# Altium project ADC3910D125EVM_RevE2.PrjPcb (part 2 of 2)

## Sheet ADC3910D125EVM_USB_Control_RevE2.SchDoc
size 431 x 279 mm; Date: Not shown in title block; ApprovedBy: Not shown in title block; CheckedBy: Not shown in title block; Author: Not shown in title block; CompanyName: Not shown in title block; Engineer: Not shown in title block; Organization: Not shown in title block; Address1: Not shown in title block; Address2: Not shown in title block; Address3: Not shown in title block; Address4: Not shown in title block; DocumentNumber: 3; Revision: Use project parameter SCH_Rev; SheetNumber: 5; SheetTotal: 7; PageSetup: Record=PageOptions¦CenterHorizontal=True¦CenterVertical=True¦PrintScale=1.00¦XCorrection=1.00¦YCorrection=1.00¦PrintKind=0¦BorderSize=5000000¦LeftOffset=0¦BottomOffset=0¦Orientation=2¦PaperLength=1000¦PaperWidth=1000¦Scale=100¦PaperSource=15¦PrintQuality=600¦MediaType=1¦DitherType=10¦PaperKind=Letter¦PrintScaleMode=1
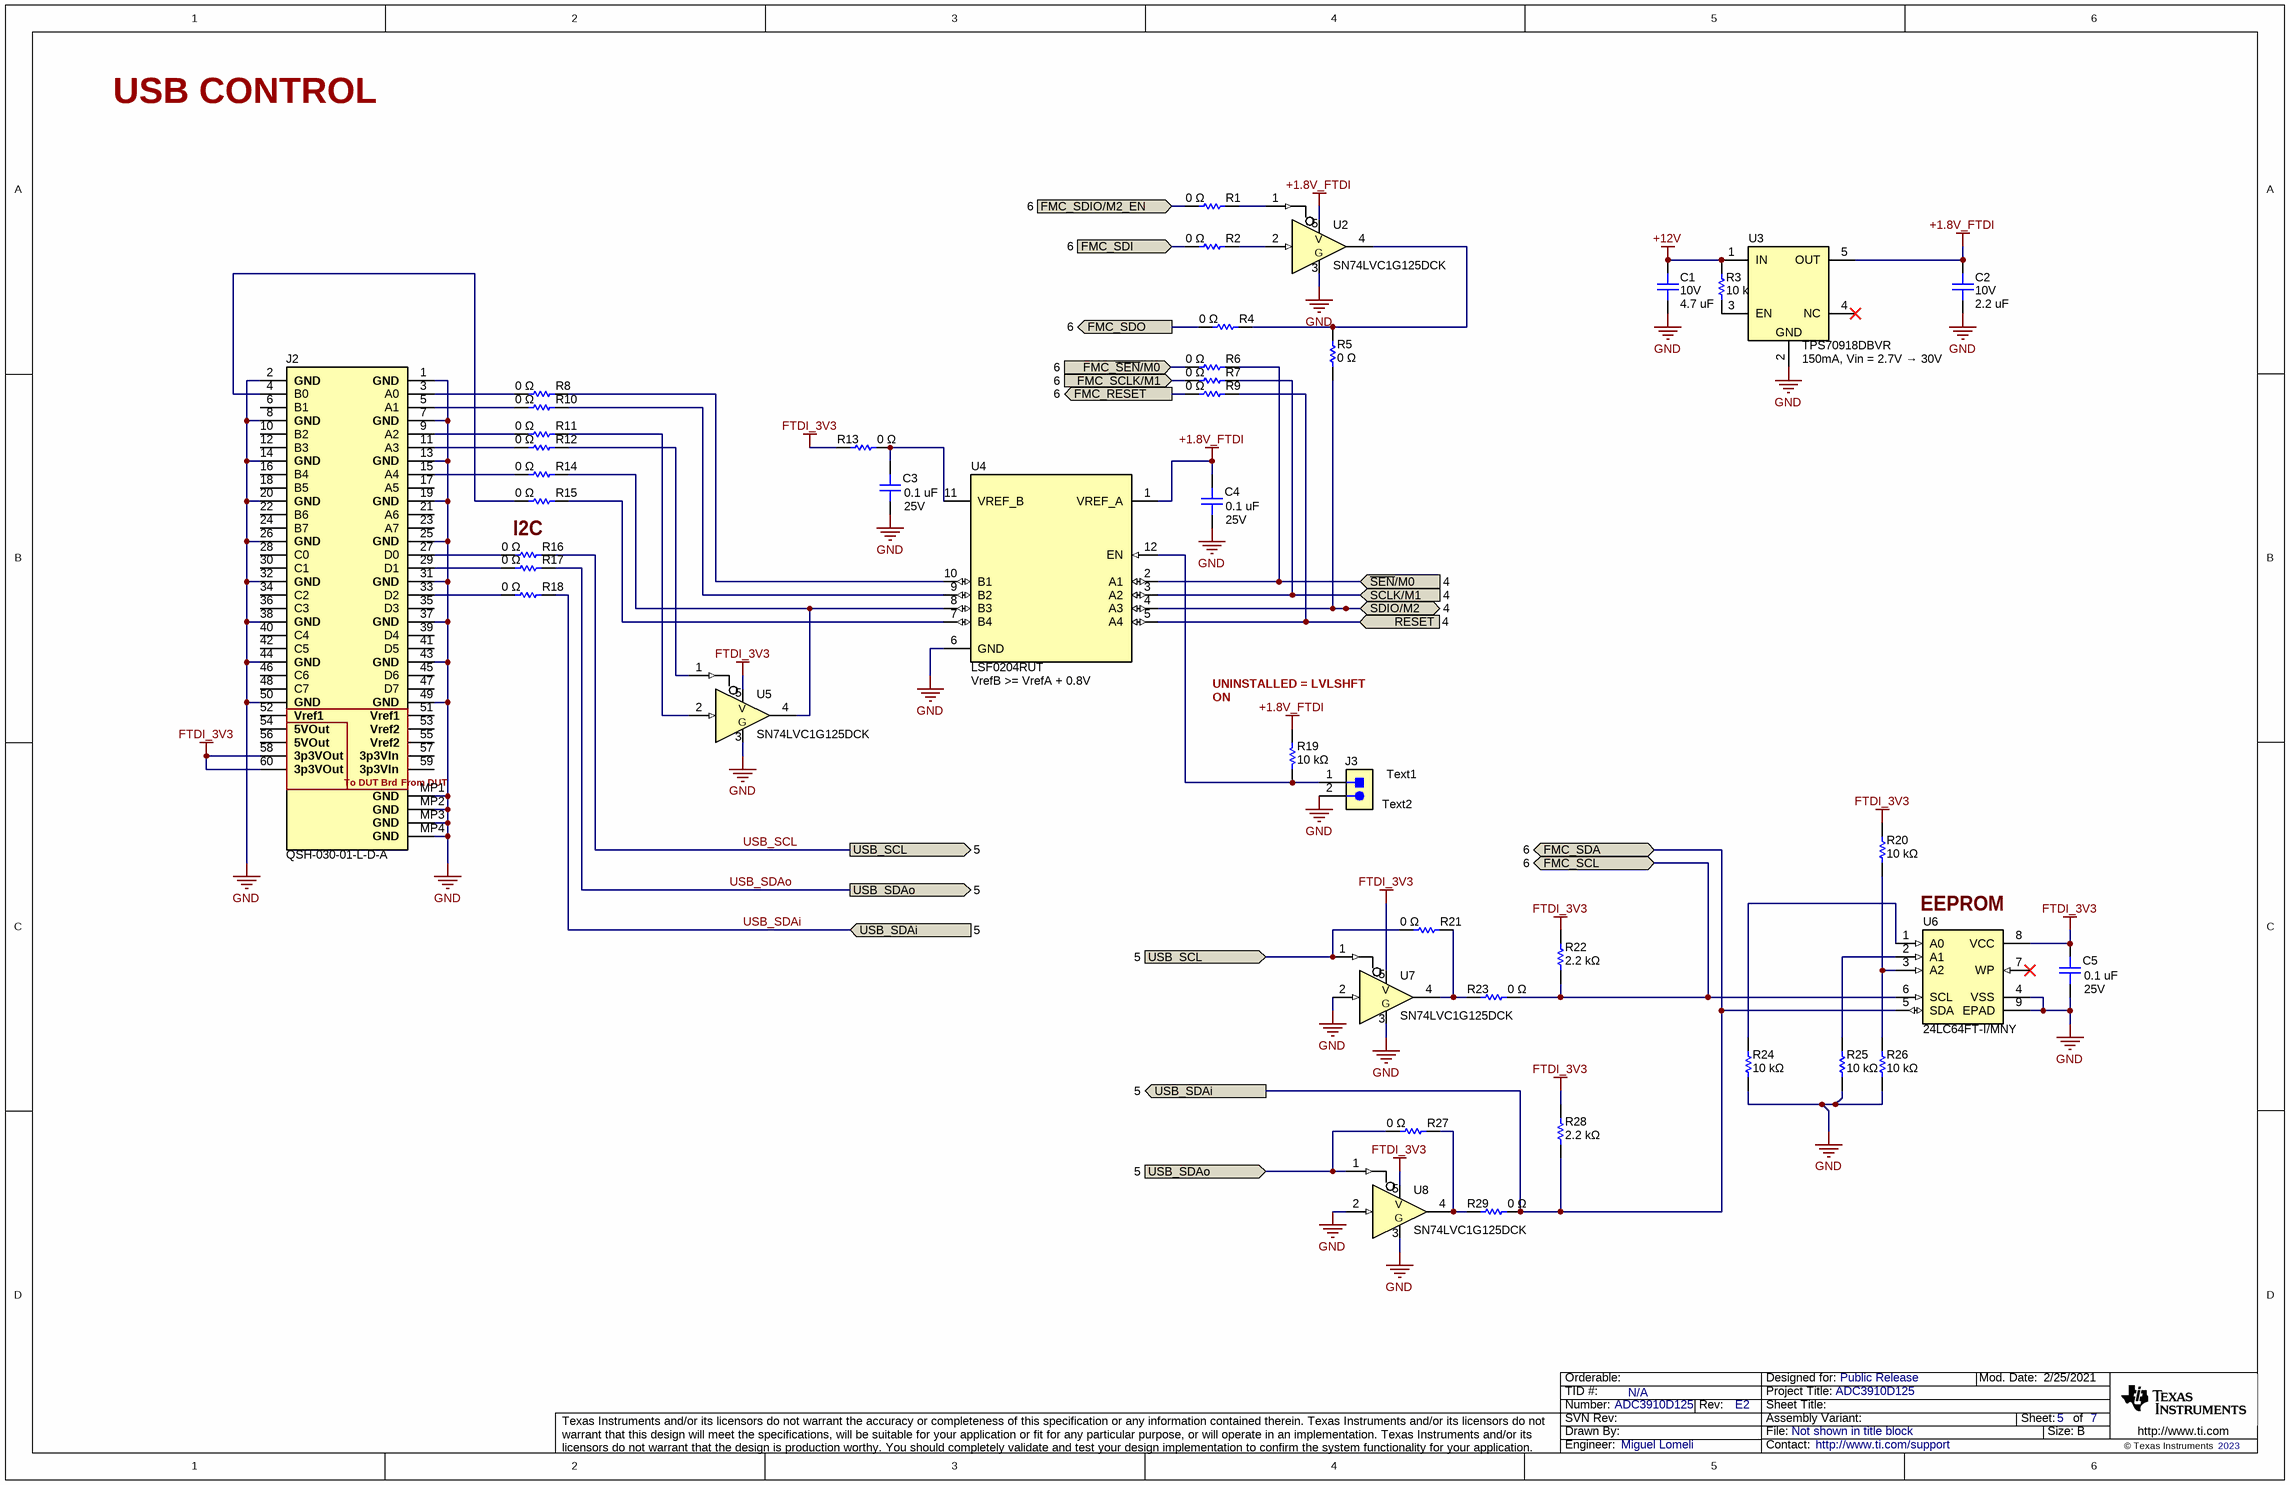
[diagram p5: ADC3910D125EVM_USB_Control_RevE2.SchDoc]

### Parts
C1  value 4.7 uF  Voltage - Rated: 10V  [0402L_cap]  (hidden comment: C1005X5R1A475K050BC)
C2  value 2.2 uF  Voltage - Rated: 10V  [0402L_cap]  (hidden comment: CM05X5R225K10AH)
C3  value 0.1 uF  Voltage - Rated: 25V  [0402L_cap]  (hidden comment: GRT155R71E104KE01J)
C4  value 0.1 uF  Voltage - Rated: 25V  [0402L_cap]  (hidden comment: GRT155R71E104KE01J)
C5  value 0.1 uF  Voltage - Rated: 25V  [0402L_cap]  (hidden comment: GRT155R71E104KE01J)
J2  QSH-030-01-L-D-A  [FTDI_Dongle_003]
J3  PBC02SAAN  [PBC02SAAN]  (value not drawn)
R1  value 0 Ω  [0201]  (hidden comment: ERJ-1GN0R00C)
R2  value 0 Ω  [0201]  (hidden comment: ERJ-1GN0R00C)
R3  value 10 kΩ  [0402L]  (hidden comment: ERJ-2RKF1002X)
R4  value 0 Ω  [0201]  (hidden comment: ERJ-1GN0R00C)
R5  value 0 Ω  [0201]  (hidden comment: ERJ-1GN0R00C)
R6  value 0 Ω  [0201]  (hidden comment: ERJ-1GN0R00C)
R7  value 0 Ω  [0201]  (hidden comment: ERJ-1GN0R00C)
R8  value 0 Ω  [0402L]  (hidden comment: ERJ-2GE0R00X)
R9  value 0 Ω  [0201]  (hidden comment: ERJ-1GN0R00C)
R10  value 0 Ω  [0402L]  (hidden comment: ERJ-2GE0R00X)
R11  value 0 Ω  [0402L]  (hidden comment: ERJ-2GE0R00X)
R12  value 0 Ω  [0402L]  (hidden comment: ERJ-2GE0R00X)
R13  value 0 Ω  [0402L]  (hidden comment: ERJ-2GE0R00X)
R14  value 0 Ω  [0402L]  (hidden comment: ERJ-2GE0R00X)
R15  value 0 Ω  [0402L]  (hidden comment: ERJ-2GE0R00X)
R16  value 0 Ω  [0402L]  (hidden comment: ERJ-2GE0R00X)
R17  value 0 Ω  [0402L]  (hidden comment: ERJ-2GE0R00X)
R18  value 0 Ω  [0402L]  (hidden comment: ERJ-2GE0R00X)
R19  value 10 kΩ  [0402L]  (hidden comment: ERJ-2GEJ103X)
R20  value 10 kΩ  [0402L]  (hidden comment: ERJ-2GEJ103X)
R21  value 0 Ω  [0201]  (hidden comment: ERJ-1GN0R00C)
R22  value 2.2 kΩ  [0402L]  (hidden comment: ERJ-2GEJ222X)
R23  value 0 Ω  [0402L]  (hidden comment: ERJ-2GE0R00X)
R24  value 10 kΩ  [0402L]  (hidden comment: ERJ-2GEJ103X)
R25  value 10 kΩ  [0402L]  (hidden comment: ERJ-2GEJ103X)
R26  value 10 kΩ  [0402L]  (hidden comment: ERJ-2GEJ103X)
R27  value 0 Ω  [0201]  (hidden comment: ERJ-1GN0R00C)
R28  value 2.2 kΩ  [0402L]  (hidden comment: ERJ-2GEJ222X)
R29  value 0 Ω  [0402L]  (hidden comment: ERJ-2GE0R00X)
U2  SN74LVC1G125DCK  [DCK0005A]
U3  TPS70918DBVR  Text1: 150mA, Vin = 2.7V → 30V  [DBV0005A]
U4  LSF0204RUT  Text1: VrefB >= VrefA + 0.8V  [RUT0012A]
U5  SN74LVC1G125DCK  [DCK0005A]
U6  24LC64FT-I/MNY  [TDFN8]
U7  SN74LVC1G125DCK  [DCK0005A]
U8  SN74LVC1G125DCK  [DCK0005A]

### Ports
FMC_RESET (out, see 6), FMC_SCL (bidir, see 6), FMC_SCLK/M1 (in, see 6), FMC_SDA (bidir, see 6), FMC_SDI (in, see 6), FMC_SDIO/M2_EN (in, see 6), FMC_SDO (out, see 6), FMC_~{SEN}/M0 (in, see 6), RESET (in, see 4), SCLK/M1 (in, see 4), SDIO/M2 (bidir, see 4), USB_SCL (in, see 5), USB_SCL (out, see 5), USB_SDAi (in, see 5), USB_SDAi (out, see 5), USB_SDAo (in, see 5), USB_SDAo (out, see 5), ~{SEN}/M0 (in, see 4)

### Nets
+1.8V_FTDI: C2.2 C4.2 R19.2 U2.5(VCC) U3.5(OUT) U4.1(VREF_A)
+12V: C1.2 R3.2 U3.1(IN)
FTDI_3V3: C5.2 J2.58(3p3VOut) J2.60(3p3VOut) R13.1 R20.2 R22.2 R28.2 U5.5(VCC) U6.8(VCC) U7.5(VCC) U8.5(VCC)
GND: C1.1 C2.1 C3.1 C4.1 C5.1 J2.1(GND) J2.2(GND) J2.7(GND) J2.8(GND) J2.13(GND) J2.14(GND) J2.19(GND) J2.20(GND) J2.25(GND) J2.26(GND) J2.31(GND) J2.32(GND) J2.37(GND) J2.38(GND) J2.43(GND) J2.44(GND) J2.49(GND) J2.50(GND) J2.MP1(GND) J2.MP2(GND) J2.MP3(GND) J2.MP4(GND) J3.2 R24.1 R25.1 R26.1 U2.3(GND) U3.2(GND) U4.6(GND) U5.3(GND) U6.4(VSS) U6.9(EPAD) U7.2(A) U7.3(GND) U8.2(A) U8.3(GND)
FMC_RESET: R9.1 ; port FMC_RESET
FMC_~{SEN}/M0: R6.1 ; port FMC_~{SEN}/M0
FMC_SCL: R22.1 R23.2 U6.6(SCL) ; port FMC_SCL
FMC_SCLK/M1: R7.1 ; port FMC_SCLK/M1
FMC_SDI: R2.1 ; port FMC_SDI
FMC_SDIO/M2_EN: R1.1 ; port FMC_SDIO/M2_EN
FMC_SDO: R4.1 ; port FMC_SDO
RESET: R9.2 U4.5(A4) ; port RESET
~{SEN}/M0: R6.2 U4.2(A1) ; port ~{SEN}/M0
SCLK/M1: R7.2 U4.3(A2) ; port SCLK/M1
SDIO/M2: R5.1 U4.4(A3) ; port SDIO/M2
USB_SCL: R16.2 R21.1 U7.1(~{OE}) ; port USB_SCL
USB_SDAi: R18.2 R28.1 R29.2 U6.5(SDA) ; port USB_SDAi, port FMC_SDA
USB_SDAo: R17.2 R27.1 U8.1(~{OE}) ; port USB_SDAo
NetC3_2: C3.2 R13.2 U4.11(VREF_B)
NetJ2_3: J2.3(A0) R8.1
NetJ2_4: J2.4(B0) R15.1
NetJ2_5: J2.5(A1) R10.1
NetJ2_9: J2.9(A2) R11.1
NetJ2_11: J2.11(A3) R12.1
NetJ2_15: J2.15(A4) R14.1
NetJ2_27: J2.27(D0) R16.1
NetJ2_29: J2.29(D1) R17.1
NetJ2_33: J2.33(D2) R18.1
NetJ3_1: J3.1 R19.1 U4.12(EN)
NetR1_2: R1.2 U2.1(~{OE})
NetR2_2: R2.2 U2.2(A)
NetR3_1: R3.1 U3.3(EN)
NetR4_2: R4.2 R5.2 U2.4(Y)
NetR8_2: R8.2 U4.10(B1)
NetR10_2: R10.2 U4.9(B2)
NetR11_2: R11.2 U5.2(A)
NetR12_2: R12.2 U5.1(~{OE})
NetR14_2: R14.2 U4.8(B3) U5.4(Y)
NetR15_2: R15.2 U4.7(B4)
NetR20_1: R20.1 R26.2 U6.3(A2)
NetR21_2: R21.2 R23.1 U7.4(Y)
NetR24_2: R24.2 U6.1(A0)
NetR25_2: R25.2 U6.2(A1)
NetR27_2: R27.2 R29.1 U8.4(Y)

Not connected (* = marked no-connect by the designer): J2 6(B1) 10(B2) 12(B3) 16(B4) 17(A5) 18(B5) 21(A6) 22(B6) 23(A7) 24(B7) 28(C0) 30(C1) 34(C2) 35(D3) 36(C3) 39(D4) 40(C4) 41(D5) 42(C5) 45(D6) 46(C6) 47(D7) 48(C7) 51(Vref1) 52(Vref1) 53(Vref2) 54(5VOut) 55(Vref2) 56(5VOut) 57(3p3VIn) 59(3p3VIn); U3 4(NC)*; U6 7(WP)*

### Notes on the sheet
- USB CONTROL
- I2C
- (near R19) UNINSTALLED = LVLSHFT ON
  INSTALLED = LVLSHFT OFF
- (near U6) EEPROM

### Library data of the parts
C1 = capcc03298: CAP CER 4.7UF 10V X5R 0402; Manufacturer: TDK Corporation; CompType: Capacitor Ceramic; Tolerance: ±10%; SizeX_mm: 1; SizeY_mm: 0.5; SizeZ_mm: 0.65
C2 = capcc03230: CAP CER 2.2UF 10V X5R 0402; Manufacturer: KYOCERA AVX; CompType: Capacitor Ceramic; Tolerance: ±10%; SizeX_mm: 1; SizeY_mm: 0.5; SizeZ_mm: 0.55
C3-C5 = capcc09401: CAP CER 0.1UF 25V X7R 0402; Manufacturer: Murata; SizeZ_mm: 0.7; SizeX_mm: 1; SizeY_mm: 0.5; CompType: Capacitor Ceramic; Tolerance: ±10%
J2 = cmp00061: FTDI Dongle EVM Mating connector and standoff holes; Manufacturer: Samtec
J3 = cmp00014: Header, 100mil, 2x1, Gold, TH; Manufacturer: Sullins Connector Solutions; Pitch (mm): 2.54
R1 R2 R4-R7 R9 R21 R27 = RSMD020101699: RES SMD 0 OHM JUMPER 1/20W 0201; Manufacturer: Panasonic Electronic Components; CompType: Resistor SMD; Power (Watts): 0.05W, 1/20W
R3 = RSMD040200314: RES SMD 10K OHM 1% 1/10W 0402; Manufacturer: Panasonic Electronic Components; Power (Watts): 0.1W, 1/10W; Temperature Coefficient: ±100ppm/°C; SizeX_mm: 1; SizeY_mm: 0.5; SizeZ_mm: 0.4; CompType: Resistor SMD
R8 R10-R18 R23 R29 = RSMD040200001: RES SMD 0 OHM JUMPER 1/10W 0402; Manufacturer: Panasonic Electronic Components; CompType: Resistor SMD; Power (Watts): 0.1W, 1/10W; SizeX_mm: 1; SizeY_mm: 0.5; SizeZ_mm: 0.4
R19 R20 R24-R26 = RSMD040200306: RES SMD 10K OHM 5% 1/10W 0402; Manufacturer: Panasonic Electronic Components; CompType: Resistor SMD; Power (Watts): 0.1W, 1/10W; Temperature Coefficient: ±200ppm/°C; SizeX_mm: 1; SizeY_mm: 0.5; SizeZ_mm: 0.4
R22 R28 = RSMD040201206: RES SMD 2.2K OHM 5% 1/10W 0402; Manufacturer: Panasonic Electronic Components; CompType: Resistor SMD; Power (Watts): 0.1W, 1/10W; Temperature Coefficient: ±200ppm/°C; SizeX_mm: 1; SizeY_mm: 0.5; SizeZ_mm: 0.4
U2 U5 U7 U8 = cmp00143: Single Bus Buffer Gate With 3-State Outputs; Manufacturer: Texas Instruments
U3 = cmp00355: 150-mA, 30-V, ultra-low-IQ, low-dropout voltage regulator with reverse current protection and enable; Manufacturer: Texas Instruments; Alt PartNumber: TPS70918DBVT; CompType: LDO
U4 = cmp00182: 4-Bit Bidirectional Multi-Voltage Level Translator for Open-Drain & Push- Pull; Manufacturer: Texas Instruments; CompType: Level Shifter
U6 = cmp00154: EEPROM 64K 8KX8 1.8V SER EE IND 1/4AWP RPO; Manufacturer: Microchip

## Sheet ADC3910D125EVM_TSW1418_Header_RevE2.SchDoc
size 431 x 279 mm; Date: Not shown in title block; ApprovedBy: Not shown in title block; CheckedBy: Not shown in title block; Author: Not shown in title block; CompanyName: Not shown in title block; Engineer: Not shown in title block; Organization: Not shown in title block; Address1: Not shown in title block; Address2: Not shown in title block; Address3: Not shown in title block; Address4: Not shown in title block; DocumentNumber: 4; Revision: Use project parameter SCH_Rev; SheetNumber: 6; SheetTotal: 7; PageSetup: Record=PageOptions¦CenterHorizontal=True¦CenterVertical=True¦PrintScale=1.00¦XCorrection=1.00¦YCorrection=1.00¦PrintKind=0¦BorderSize=5000000¦LeftOffset=0¦BottomOffset=0¦Orientation=2¦PaperLength=1000¦PaperWidth=1000¦Scale=100¦PaperSource=15¦PrintQuality=600¦MediaType=1¦DitherType=10¦PaperKind=Letter¦PrintScaleMode=1
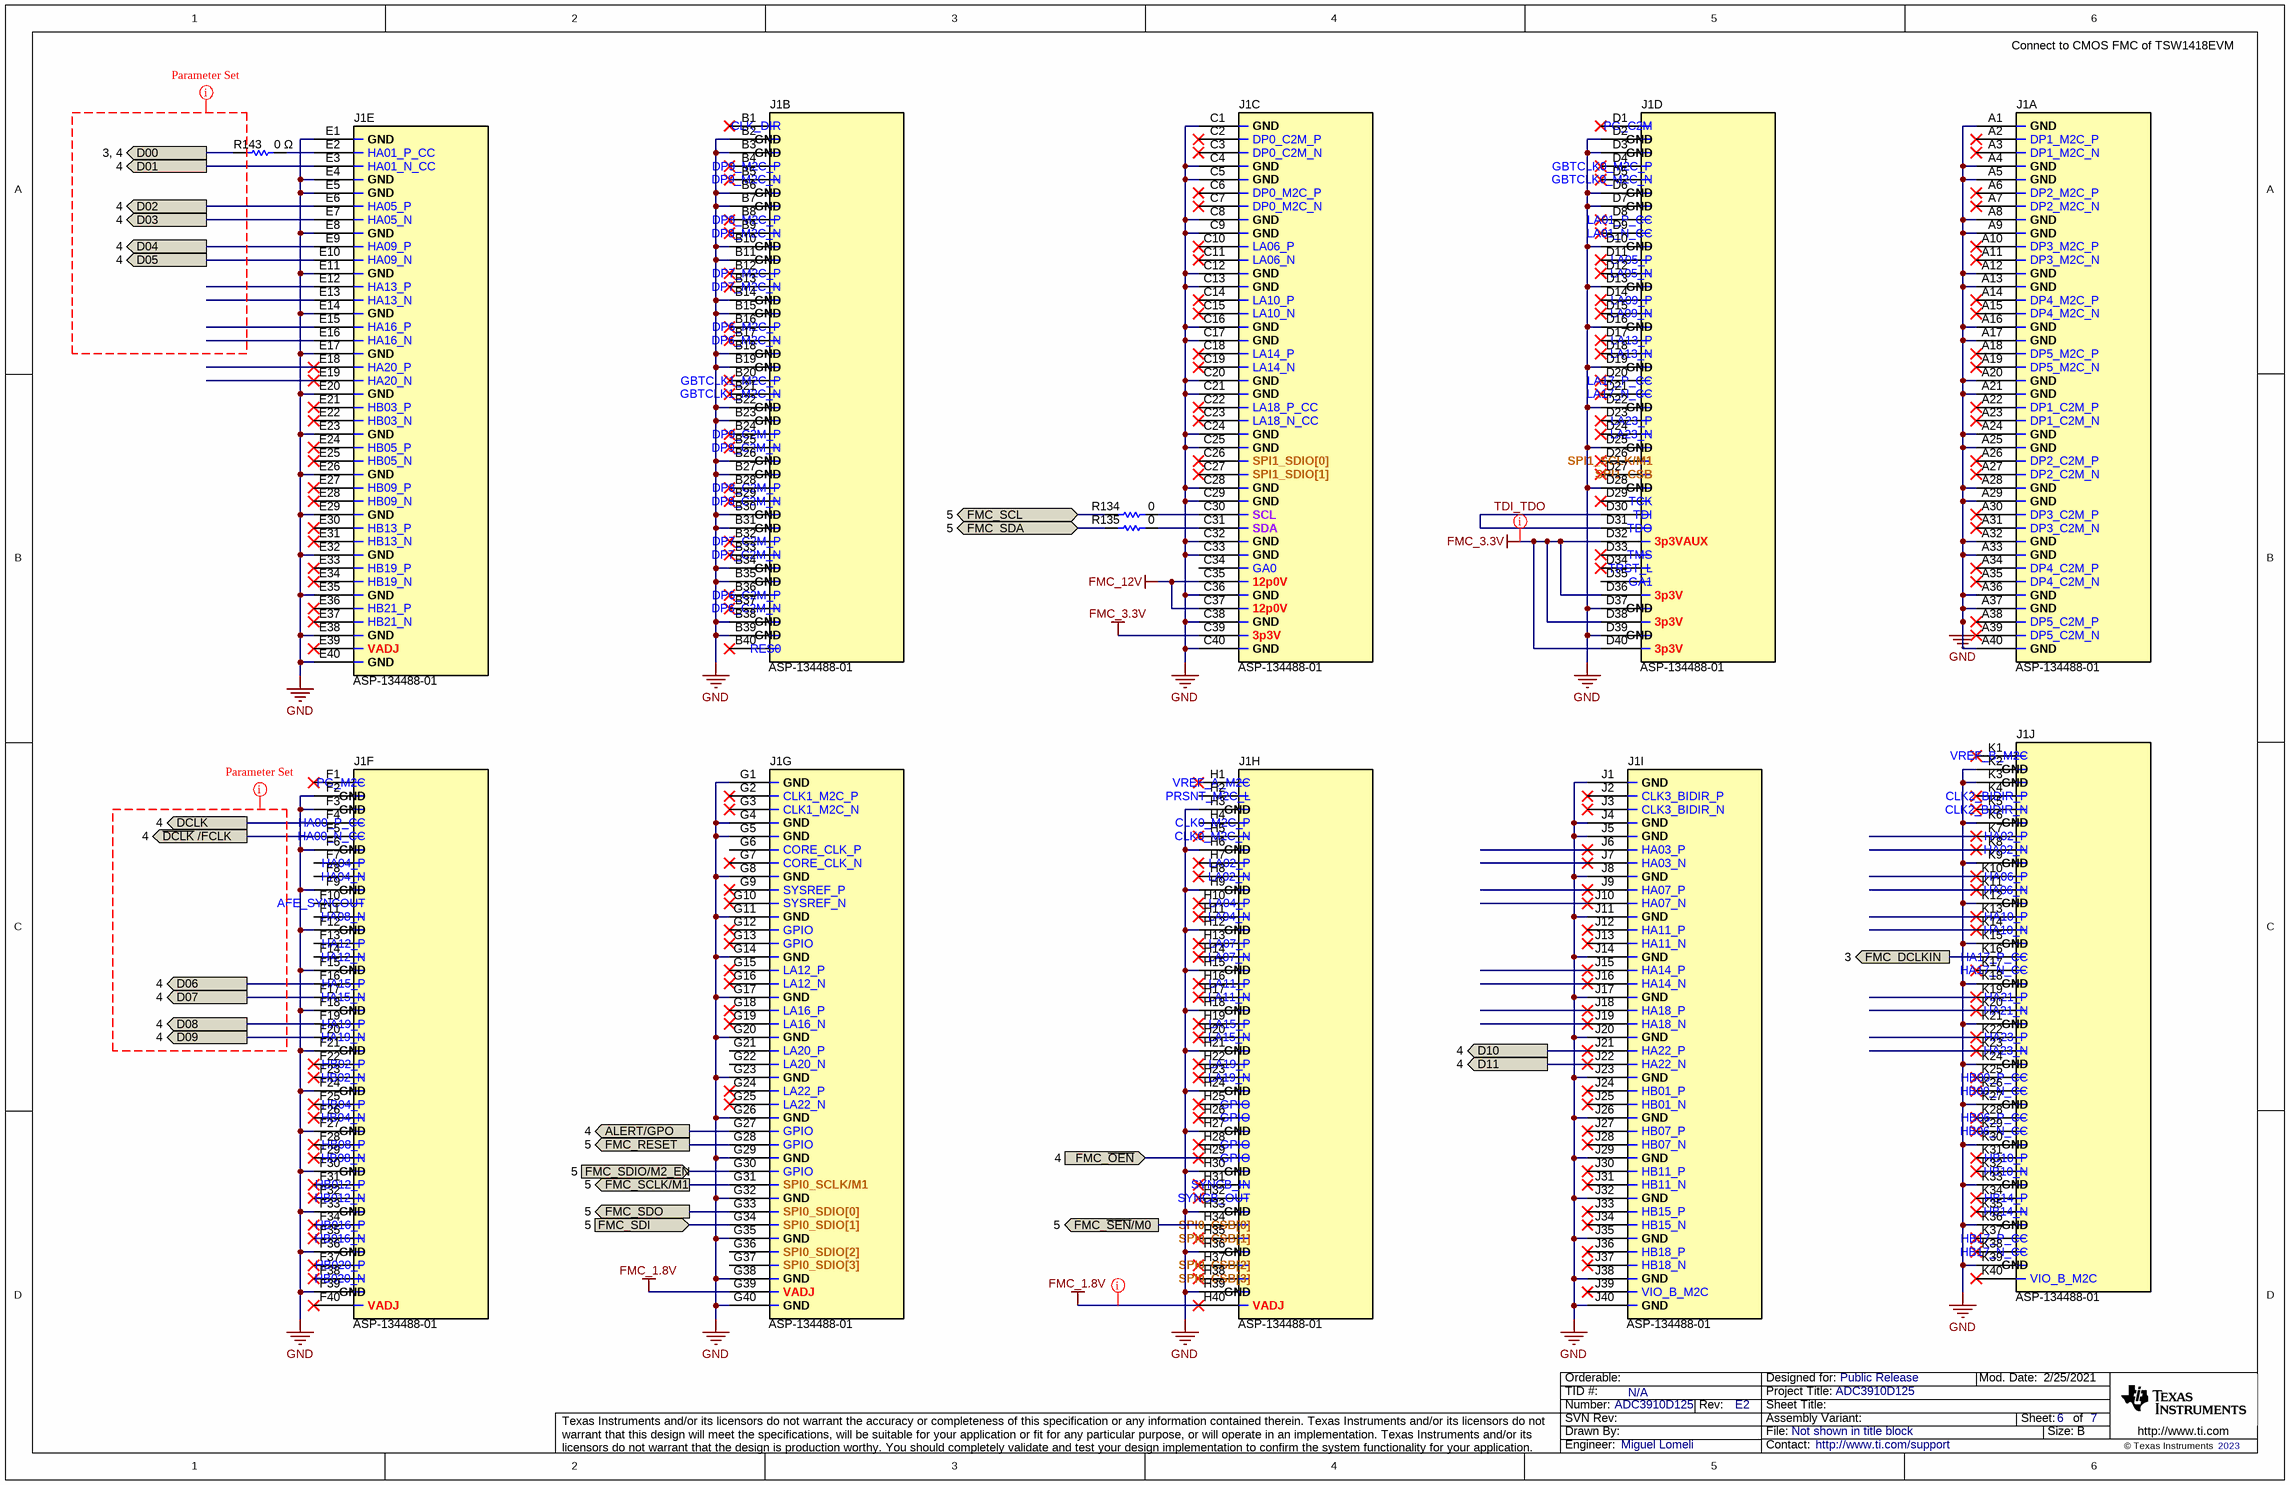
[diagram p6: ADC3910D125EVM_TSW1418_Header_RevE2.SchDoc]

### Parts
J1  ASP-134488-01  [SAMTEC_ASP-134488-01]  (parts A,B,C,D,E,F,G,H,I,J of 10)
R134  ValueDisplayed: 0  [0201L]  (hidden comment: CRCW02010000Z0ED)
R135  ValueDisplayed: 0  [0201L]  (hidden comment: CRCW02010000Z0ED)
R143  value 0 Ω  [0402L]  (hidden comment: ERJ-2GE0R00X)

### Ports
ALERT/GPO (out, see 4), D00 (out, see 3, 4), D01 (out, see 4), D02 (out, see 4), D03 (out, see 4), D04 (out, see 4), D05 (out, see 4), D06 (out, see 4), D07 (out, see 4), D08 (out, see 4), D09 (out, see 4), D10 (out, see 4), D11 (out, see 4), DCLK (out, see 4), FMC_DCLKIN (out, see 3), FMC_RESET (out, see 5), FMC_SCL (bidir, see 5), FMC_SCLK/M1 (out, see 5), FMC_SDA (bidir, see 5), FMC_SDI (in, see 5), FMC_SDIO/M2_EN (in, see 5), FMC_SDO (out, see 5), FMC_~{OEN} (in, see 4), FMC_~{SEN}/M0 (out, see 5), ~{DCLK} /FCLK (out, see 4)

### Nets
FMC_1.8V: J1.G39 J1.H40
FMC_3.3V: J1.C39 J1.D32 J1.D36 J1.D38 J1.D40
FMC_12V: J1.C35 J1.C37
GND: J1.A1 J1.A4 J1.A5 J1.A8 J1.A9 J1.A12 J1.A13 J1.A16 J1.A17 J1.A20 J1.A21 J1.A24 J1.A25 J1.A28 J1.A29 J1.A32 J1.A33 J1.A36 J1.A37 J1.A40 J1.B2 J1.B3 J1.B6 J1.B7 J1.B10 J1.B11 J1.B14 J1.B15 J1.B18 J1.B19 J1.B22 J1.B23 J1.B26 J1.B27 J1.B30 J1.B31 J1.B34 J1.B35 J1.B38 J1.B39 J1.C1 J1.C4 J1.C5 J1.C8 J1.C9 J1.C12 J1.C13 J1.C16 J1.C17 J1.C20 J1.C21 J1.C24 J1.C25 J1.C28 J1.C29 J1.C32 J1.C33 J1.C36 J1.C38 J1.C40 J1.D2 J1.D3 J1.D6 J1.D7 J1.D10 J1.D13 J1.D16 J1.D19 J1.D22 J1.D25 J1.D28 J1.D37 J1.D39 J1.E1 J1.E4 J1.E5 J1.E8 J1.E11 J1.E14 J1.E17 J1.E20 J1.E23 J1.E26 J1.E29 J1.E32 J1.E35 J1.E38 J1.E40 J1.F2 J1.F3 J1.F6 J1.F9 J1.F12 J1.F15 J1.F18 J1.F21 J1.F24 J1.F27 J1.F30 J1.F33 J1.F36 J1.F39 J1.G1 J1.G4 J1.G5 J1.G8 J1.G11 J1.G14 J1.G17 J1.G20 J1.G23 J1.G26 J1.G29 J1.G32 J1.G35 J1.G38 J1.G40 J1.H3 J1.H6 J1.H9 J1.H12 J1.H15 J1.H18 J1.H21 J1.H24 J1.H27 J1.H30 J1.H33 J1.H36 J1.H39 J1.J1 J1.J4 J1.J5 J1.J8 J1.J11 J1.J14 J1.J17 J1.J20 J1.J23 J1.J26 J1.J29 J1.J32 J1.J35 J1.J38 J1.J40 J1.K2 J1.K3 J1.K6 J1.K9 J1.K12 J1.K15 J1.K18 J1.K21 J1.K24 J1.K27 J1.K30 J1.K33 J1.K36 J1.K39
ALERT/GPO: J1.G27 ; port ALERT/GPO
D00: R143.1 ; port D00
D01: J1.E3 ; port D01
D02: J1.E6 ; port D02
D03: J1.E7 ; port D03
D04: J1.E9 ; port D04
D05: J1.E10 ; port D05
D06: J1.F16 ; port D06
D07: J1.F17 ; port D07
D08: J1.F19 ; port D08
D09: J1.F20 ; port D09
D10: J1.J21 ; port D10
D11: J1.J22 ; port D11
~{DCLK} /FCLK: J1.F5 ; port ~{DCLK} /FCLK
DCLK: J1.F4 ; port DCLK
FMC_DCLKIN: J1.K16 ; port FMC_DCLKIN
FMC_~{OEN}: J1.H29 ; port FMC_~{OEN}
FMC_RESET: J1.G28 ; port FMC_RESET
FMC_~{SEN}/M0: J1.H34 ; port FMC_~{SEN}/M0
FMC_SCL: R134.1 ; port FMC_SCL
FMC_SCLK/M1: J1.G31 ; port FMC_SCLK/M1
FMC_SDI: J1.G34 ; port FMC_SDI
FMC_SDIO/M2_EN: J1.G30 ; port FMC_SDIO/M2_EN
FMC_SDO: J1.G33 ; port FMC_SDO
TDI_TDO: J1.D30 J1.D31
USB_SDAi: R135.1 ; port FMC_SDA
NetJ1_C30: J1.C30 R134.2
NetJ1_C31: J1.C31 R135.2
NetJ1_E2: J1.E2 R143.2

Not connected (* = marked no-connect by the designer): J1 A2* A3* A6* A7* A10* A11* A14* A15* A18* A19* A22* A23* A26* A27* A30* A31* A34* A35* A38* A39* B1* B4* B5* B8* B9* B12* B13* B16* B17* B20* B21* B24* B25* B28* B29* B32* B33* B36* B37* B40* C2* C3* C6* C7* C10* C11* C14* C15* C18* C19* C22* C23* C26* C27* C34 D1* D4* D5* D8* D9* D11* D12* D14* D15* D17* D18* D20* D21* D23* D24* D26* D27* D29* D33* D34* D35 E12 E13 E15 E16 E18* E19* E21* E22* E24* E25* E27* E28* E30* E31* E33* E34* E36* E37* E39* F1* F7 F8 F10 F11 F13 F14 F22* F23* F25* F26* F28* F29* F31* F32* F34* F35* F37* F38* F40* G2* G3* G6 G7* G9* G10* G12* G13* G15* G16* G18* G19* G21 G22 G24* G25* G36 G37 H1* H2 H4 H5* H7* H8* H10* H11* H13* H14* H16* H17* H19* H20* H22* H23* H25* H26* H28* H31* H32* H35* H37* H38* J2* J3* J6* J7* J9* J10* J12* J13* J15* J16* J18* J19* J24* J25* J27* J28* J30* J31* J33* J34* J36* J37* J39* K1* K4* K5* K7* K8* K10* K11* K13* K14* K17* K19* K20* K22* K23* K25* K26* K28* K29* K31* K32* K34* K35* K37* K38* K40*

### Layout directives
net class SerialOutput: (no net found under the mark)
net class Power: FMC_1.8V, FMC_3.3V

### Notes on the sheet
- Connect to CMOS FMC of TSW1418EVM

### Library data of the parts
J1 = cmp00010: EVM Connector 40x10; Manufacturer: Samtec; Pitch (mm): 1.27
R134 R135 = CMP-0027008-4: RES, 0, 5%, 0.05 W, 0201; Manufacturer: Vishay-Dale; Power_W: 50mW; TempCo: ppm/C; Value_Code: 0000; Value: 0; EIA_Code: E24; SizeX_mm: 0.6; SizeY_mm: 0.3; SizeZ_mm: 0.26; Value2: 0.05W; SizeArea_mm2: 0.18; AEC Qualified: N; AEC Category: Q200
R143 = RSMD040200001: as R8 on sheet ADC3910D125EVM_USB_Control_RevE2

## Sheet ADC3910D125EVM_Hardware_RevE2.SchDoc
size 431 x 279 mm; Date: Not shown in title block; ApprovedBy: Not shown in title block; CheckedBy: Not shown in title block; Author: Not shown in title block; CompanyName: Not shown in title block; Engineer: Not shown in title block; Organization: Not shown in title block; Address1: Not shown in title block; Address2: Not shown in title block; Address3: Not shown in title block; Address4: Not shown in title block; DocumentNumber: 6; Revision: Use project parameter SCH_Rev; SheetNumber: 7; SheetTotal: 7; PageSetup: Record=PageOptions¦CenterHorizontal=True¦CenterVertical=True¦PrintScale=1.00¦XCorrection=1.00¦YCorrection=1.00¦PrintKind=0¦BorderSize=5000000¦LeftOffset=0¦BottomOffset=0¦Orientation=2¦PaperLength=1000¦PaperWidth=1000¦Scale=100¦PaperSource=15¦PrintQuality=600¦MediaType=1¦DitherType=10¦PaperKind=Letter¦PrintScaleMode=1
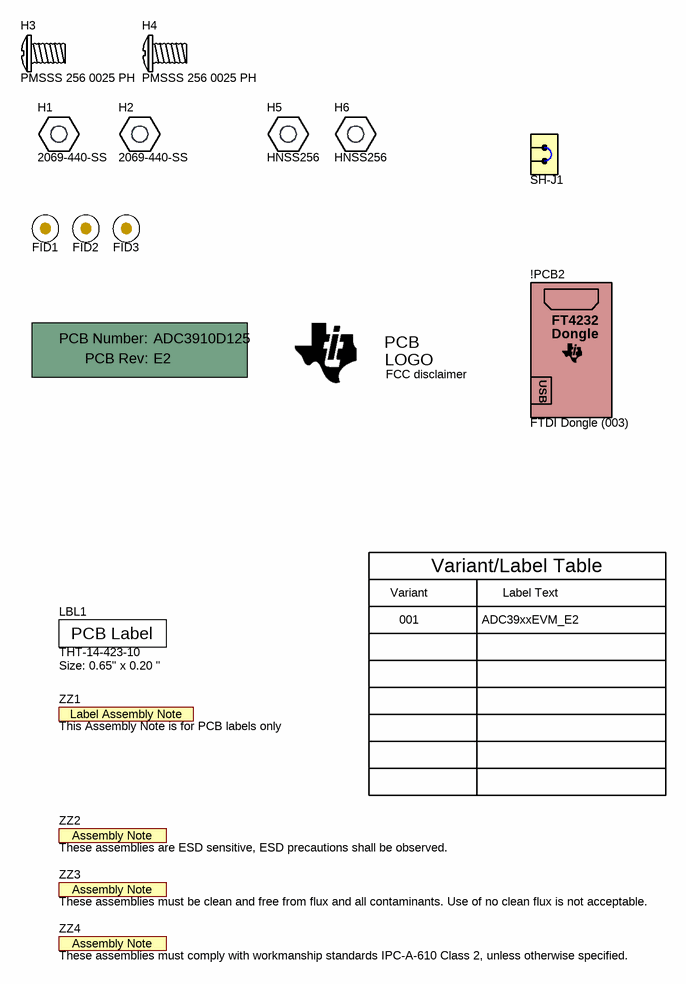
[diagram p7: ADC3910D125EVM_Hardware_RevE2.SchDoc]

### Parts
!PCB1  Printed Circuit Board  (value not drawn)  (mechanical)
!PCB2  FTDI Dongle (003)  (mechanical)
FID1  Fiducial Mark  [Fiducial10-20]  (value not drawn)  (no BOM)
FID2  Fiducial Mark  [Fiducial10-20]  (value not drawn)  (no BOM)
FID3  Fiducial Mark  [Fiducial10-20]  (value not drawn)  (no BOM)
H1  2069-440-SS  [FP-2116-440-AL_STANDOFF_HEX_1-4-MFG]
H2  2069-440-SS  [FP-2116-440-AL_STANDOFF_HEX_1-4-MFG]
H3  PMSSS 256 0025 PH  [PMSSS 256 0025]  (mechanical)
H4  PMSSS 256 0025 PH  [PMSSS 256 0025]  (mechanical)
H5  HNSS256  [HNSS256]
H6  HNSS256  [HNSS256]
LBL1  THT-14-423-10  Note: Size: 0.65" x 0.20 "  [Label_650x200]
Logo1  FCC disclaimer  [FCC_disclaimer]  (no BOM)
Logo2  Texas Instruments  [TI_Stacked_Overlay_Small]  (value not drawn)  (no BOM)
SH-J1  SPC02SYAN  [SPC02SYAN]  (value not drawn)
ZZ1  This Assembly Note is for PCB labels only  [AssemblyNoteLabel]  (no BOM)
ZZ2  These assemblies are ESD sensitive, ESD precautions shall be observed.  [AssemblyNote]  (no BOM)
ZZ3  These assemblies must be clean and free from flux and all contaminants. Use of no clean flux is not acceptable.  [AssemblyNote]  (no BOM)
ZZ4  These assemblies must comply with workmanship standards IPC-A-610 Class 2, unless otherwise specified.  [AssemblyNote]  (no BOM)

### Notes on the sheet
- Variant
- Variant/Label Table
- Label Text
- 001
- ADC39xxEVM_E2

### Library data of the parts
!PCB1 = CMP-0003618-2: Manufacturer: Any; PartNumber: ADC3910D125
!PCB2 = cmp00363: FTDI Dongle RevA Variant 003; Manufacturer: Texas Instruments; CompType: Peripheral Board
FID1-FID3 = cmp00099: Fiducial; SymbolCreator: a0412235
H1 H2 = cmp00097: Hex Standoff Threaded #4-40 Stainless Steel 1.250" (31.75mm) 1 1/4; Manufacturer: RAF Electronic Hardware
H3 H4 = cmp00096: MACHINE SCREW PAN PHILLIPS 2-56; Manufacturer: B&F Fastener Supply
H5 H6 = cmp00358: Hex Nut 3/16" Stainless Steel 2-56; Manufacturer: B&F Fastener Supply; CompType: Hex Nut
LBL1 = CMP-0003625-1: Thermal Transfer Printable Labels, 0.650" W x 0.200" H - 10,000 per roll; Manufacturer: Brady
Logo1 = CMP-0074847-1: FCC_disclaimer
Logo2 = cmp00104: Texas Instrument Corporate Signature; PartNumber: TI Bug; CompType: Logo
SH-J1 = cmp00093: 2 (1 x 2) Position Shunt Connector Black Closed Top 0.100" (2.54mm) Gold; Manufacturer: Sullins; Value: 1x2; Note: You can "mate" this to a header by matching the designator.  i.e. use SH-J3 for header J3; Pitch (mm): 2.54
ZZ1 = CMP-0003616-3
ZZ2 = CMP-0077236-1
ZZ3 = CMP-0077237-1
ZZ4 = CMP-0077238-1

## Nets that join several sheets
+12V: ADC3910D125EVM_Power_RevE2 (10 pins), ADC3910D125EVM_USB_Control_RevE2 (C1.2 R3.2 U3.1)
AVDD: ADC3910D125EVM_Power_RevE2 (C6.3 C8.2 C9.2), ADC3910D125EVM_AIN_CLK_RevE2 (R81.2 R82.2), ADC3910D125EVM_DUT_RevE2 (9 pins)
FDA_3V3: ADC3910D125EVM_Power_RevE2 (C29.3 C32.2 C33.2), ADC3910D125EVM_AIN_CLK_RevE2 (R98.1 R102.2 R122.1 R126.2)
FMC_1.8V: ADC3910D125EVM_Power_RevE2 (R30.2 R40.1), ADC3910D125EVM_TSW1418_Header_RevE2 (J1.G39 J1.H40)
FMC_3.3V: ADC3910D125EVM_Power_RevE2 (R39.2), ADC3910D125EVM_TSW1418_Header_RevE2 (5 pins)
FMC_12V: ADC3910D125EVM_Power_RevE2 (SW1.3), ADC3910D125EVM_TSW1418_Header_RevE2 (J1.C35 J1.C37)
GND: ADC3910D125EVM_Power_RevE2 (60 pins), ADC3910D125EVM_AIN_CLK_RevE2 (65 pins), ADC3910D125EVM_DUT_RevE2 (19 pins), ADC3910D125EVM_USB_Control_RevE2 (41 pins), ADC3910D125EVM_TSW1418_Header_RevE2 (159 pins)
IOVDD: ADC3910D125EVM_Power_RevE2 (C16.3 C18.2 C19.2), ADC3910D125EVM_DUT_RevE2 (C44.2 R70.2 U1.27)
REF_3p3V: ADC3910D125EVM_Power_RevE2 (C21.3 C28.2 C38.2), ADC3910D125EVM_DUT_RevE2 (C49.2 R68.2 U13.4)
VCM: ADC3910D125EVM_AIN_CLK_RevE2 (10 pins), ADC3910D125EVM_DUT_RevE2 (C45.2 C46.2 TP7.1 U1.7)
ALERT/GPO: ADC3910D125EVM_DUT_RevE2 (R70.1 TP8.1 U1.20), ADC3910D125EVM_TSW1418_Header_RevE2 (J1.G27)
CLK: ADC3910D125EVM_AIN_CLK_RevE2 (C52.1 R82.1 R87.2), ADC3910D125EVM_DUT_RevE2 (R69.1)
D00: ADC3910D125EVM_AIN_CLK_RevE2 (R140.2), ADC3910D125EVM_DUT_RevE2 (R54.2), ADC3910D125EVM_TSW1418_Header_RevE2 (R143.1)
D01: ADC3910D125EVM_DUT_RevE2 (R55.2), ADC3910D125EVM_TSW1418_Header_RevE2 (J1.E3)
D02: ADC3910D125EVM_DUT_RevE2 (R56.2), ADC3910D125EVM_TSW1418_Header_RevE2 (J1.E6)
D03: ADC3910D125EVM_DUT_RevE2 (R57.2), ADC3910D125EVM_TSW1418_Header_RevE2 (J1.E7)
D04: ADC3910D125EVM_DUT_RevE2 (R58.2), ADC3910D125EVM_TSW1418_Header_RevE2 (J1.E9)
D05: ADC3910D125EVM_DUT_RevE2 (R59.2), ADC3910D125EVM_TSW1418_Header_RevE2 (J1.E10)
D06: ADC3910D125EVM_DUT_RevE2 (R60.2), ADC3910D125EVM_TSW1418_Header_RevE2 (J1.F16)
D07: ADC3910D125EVM_DUT_RevE2 (R61.2), ADC3910D125EVM_TSW1418_Header_RevE2 (J1.F17)
D08: ADC3910D125EVM_DUT_RevE2 (R62.2), ADC3910D125EVM_TSW1418_Header_RevE2 (J1.F19)
D09: ADC3910D125EVM_DUT_RevE2 (R63.2), ADC3910D125EVM_TSW1418_Header_RevE2 (J1.F20)
D10: ADC3910D125EVM_DUT_RevE2 (R64.2), ADC3910D125EVM_TSW1418_Header_RevE2 (J1.J21)
D11: ADC3910D125EVM_DUT_RevE2 (R65.2), ADC3910D125EVM_TSW1418_Header_RevE2 (J1.J22)
~{DCLK} /FCLK: ADC3910D125EVM_DUT_RevE2 (R71.2), ADC3910D125EVM_TSW1418_Header_RevE2 (J1.F5)
DCLK: ADC3910D125EVM_DUT_RevE2 (R67.2), ADC3910D125EVM_TSW1418_Header_RevE2 (J1.F4)
DCLKIN: ADC3910D125EVM_AIN_CLK_RevE2 (C51.1 R81.1 R86.2), ADC3910D125EVM_DUT_RevE2 (R72.1)
FMC_DCLKIN: ADC3910D125EVM_AIN_CLK_RevE2 (R83.2), ADC3910D125EVM_TSW1418_Header_RevE2 (J1.K16)
FMC_~{OEN}: ADC3910D125EVM_DUT_RevE2 (R80.2), ADC3910D125EVM_TSW1418_Header_RevE2 (J1.H29)
FMC_RESET: ADC3910D125EVM_USB_Control_RevE2 (R9.1), ADC3910D125EVM_TSW1418_Header_RevE2 (J1.G28)
FMC_~{SEN}/M0: ADC3910D125EVM_USB_Control_RevE2 (R6.1), ADC3910D125EVM_TSW1418_Header_RevE2 (J1.H34)
FMC_SCL: ADC3910D125EVM_USB_Control_RevE2 (R22.1 R23.2 U6.6), ADC3910D125EVM_TSW1418_Header_RevE2 (R134.1)
FMC_SCLK/M1: ADC3910D125EVM_USB_Control_RevE2 (R7.1), ADC3910D125EVM_TSW1418_Header_RevE2 (J1.G31)
FMC_SDI: ADC3910D125EVM_USB_Control_RevE2 (R2.1), ADC3910D125EVM_TSW1418_Header_RevE2 (J1.G34)
FMC_SDIO/M2_EN: ADC3910D125EVM_USB_Control_RevE2 (R1.1), ADC3910D125EVM_TSW1418_Header_RevE2 (J1.G30)
FMC_SDO: ADC3910D125EVM_USB_Control_RevE2 (R4.1), ADC3910D125EVM_TSW1418_Header_RevE2 (J1.G33)
INAM: ADC3910D125EVM_AIN_CLK_RevE2 (C63.1 R103.2), ADC3910D125EVM_DUT_RevE2 (U1.11)
INAP: ADC3910D125EVM_AIN_CLK_RevE2 (C57.2 R91.2), ADC3910D125EVM_DUT_RevE2 (U1.10)
INBM: ADC3910D125EVM_AIN_CLK_RevE2 (C82.1 R125.2), ADC3910D125EVM_DUT_RevE2 (U1.15)
INBP: ADC3910D125EVM_AIN_CLK_RevE2 (C77.2 R114.2), ADC3910D125EVM_DUT_RevE2 (U1.14)
RESET: ADC3910D125EVM_DUT_RevE2 (R78.1 R79.2 SW2.2), ADC3910D125EVM_USB_Control_RevE2 (R9.2 U4.5)
~{SEN}/M0: ADC3910D125EVM_DUT_RevE2 (J5.4 R77.1 R137.2), ADC3910D125EVM_USB_Control_RevE2 (R6.2 U4.2)
SCLK/M1: ADC3910D125EVM_DUT_RevE2 (J5.6 R75.1 R138.2), ADC3910D125EVM_USB_Control_RevE2 (R7.2 U4.3)
SDIO/M2: ADC3910D125EVM_DUT_RevE2 (J5.8 R76.1 R139.2), ADC3910D125EVM_USB_Control_RevE2 (R5.1 U4.4)
USB_SDAi: ADC3910D125EVM_USB_Control_RevE2 (R18.2 R28.1 R29.2 U6.5), ADC3910D125EVM_TSW1418_Header_RevE2 (R135.1)

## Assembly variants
001: not fitted C37 C53 C54 C66 C67 C74 C75 C87 C88 F1 FID1 FID2 FID3 R1 R2 R4 R5 R6 R7 R9 R20 R21 R27 R30 R35 R38 R39 R40 R44 R50 R68 R83 R89 R90 R98 R104 R107 R112 R113 R122 R127 R130 R140 R146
